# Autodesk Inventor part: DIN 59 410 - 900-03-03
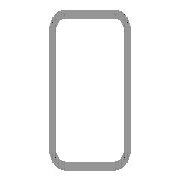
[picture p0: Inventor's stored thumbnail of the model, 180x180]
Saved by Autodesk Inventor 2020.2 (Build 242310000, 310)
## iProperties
Manager: www.cadconsulting.pl
Company: Fabian Stasiak CAD Consulting
Created: 2015-02
Part Number: DIN 59 410 - 900-03-03
Material: Stal, miękka
Description: Rurki stalowe o przekroju prostokątnym formowane na gorąco
Document SubType Name: Modellieren
Standard: DIN 59 410
Designer: F.Stasiak
Standards Organization: DIN
Language: pl-PL
Size Designation: 120x60x5-694
Categories: <MemberInstance><Categories><Category DisplayName="Kształtowniki konstrukcyjne" InternalName="089c4875-fa83-4c05-b084-43b9cc11f5ed" Mnemonic="GRDR"><CategoryPar
Stock Number: 120x60x5
Density: 7.85 g/cm^3
Appearance: Częściowo polerowany
Catalog Web Link: www.expertbooks.pl
IsCustomPart: 1
G_L: 694,000 mm
Author: F.Stasiak
Subject: Zbiór ćwiczeń. Autodesk Inventor 2020. Kurs Professional
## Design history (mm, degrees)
node "Płaszczyzna początkowa"
node "Płaszczyzna końcowa"
sketch "Szkic1"
  geometry: L1 (-20, 60)-(20, 60); L2 (30, 50)-(30, -50); L3 (20, -60)-(-20, -60); L4 (-30, -50)-(-30, 50); L5 (-21.87, 0)-(21.87, 0) reference; L6 (0, -35.87)-(0, 35.87) reference; L7 (-20, 55)-(20, 55); L8 (25, 50)-(25, -50); L9 (20, -55)-(-20, -55); L10 (-25, -50)-(-25, 50); A1 r 10 centre (-20, 50) between (-20, 60) and (-30, 50); A2 r 10 centre (20, 50) between (30, 50) and (20, 60); A3 r 10 centre (20, -50) between (20, -60) and (30, -50); A4 r 10 centre (-20, -50) between (-30, -50) and (-20, -60); A5 r 5 centre (-20, 50) between (-20, 55) and (-25, 50); A6 r 5 centre (20, 50) between (25, 50) and (20, 55); A7 r 5 centre (20, -50) between (20, -55) and (25, -50); A8 r 5 centre (-20, -50) between (-25, -50) and (-20, -55); 3 further points
  constraints: 16 end point, 16 point on circle, 8 centre point, 8 tangent, 6 point on line, 4 parallel, 3 equal radius, 2 perpendicular, 1 horizontal, 7 other
  dimensions: "b" = 60 distance of point (-30, 60) point (30, 60); "ParH" = 120 distance of point (30, 60) point (30, -60); "msp_r" = 10 radius of A1 (= 2 x ParT); "d8" = 30 distance between parallel lines of L4 L6 (= 0.5 x b); "d9" = 60 distance between parallel lines of L5 L1 (= 0.5 x ParH); "d10" = 5 distance between parallel lines of L4 L10 (= ParT)
extrude "Bryła" new body sketch "Szkic1" taper "d4" = 0 deg; stored distance "NLG" = 10
node "Driven Length"
  sketch "Sketch2"
    geometry: L1 (0, 0)-(10, 0) reference
    constraints: 2 end point, 1 horizontal
  workplane "Work Plane3"
  sketch "Sketch3"
    geometry: L1 (-2, 0)-(12, 0) reference; L2 (-2, 694)-(12, 694) reference
    dimensions: "d14" = 694 distance between parallel lines of L1 L2 (derived)
body "Solid1"
other parameters: "ParT" = 5, "G_OFFSET_START" = 0 [user parameter; used in 1 equation term], "G_OFFSET_END" = 0 [user parameter; used in 1 equation term], "d11" = 0 (computed from G_OFFSET_START), "d12" = 694 (= G_OFFSET_END + B_L), "G_L" = 694 (= d14) [user parameter], "B_L" = 694 [user parameter; used in 1 equation term], "d13" = 90 deg
